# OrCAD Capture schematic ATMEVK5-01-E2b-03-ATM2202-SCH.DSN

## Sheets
1 1. TITLE: title: ATM2202 EVALUATION BOARD; rev: E2b-03
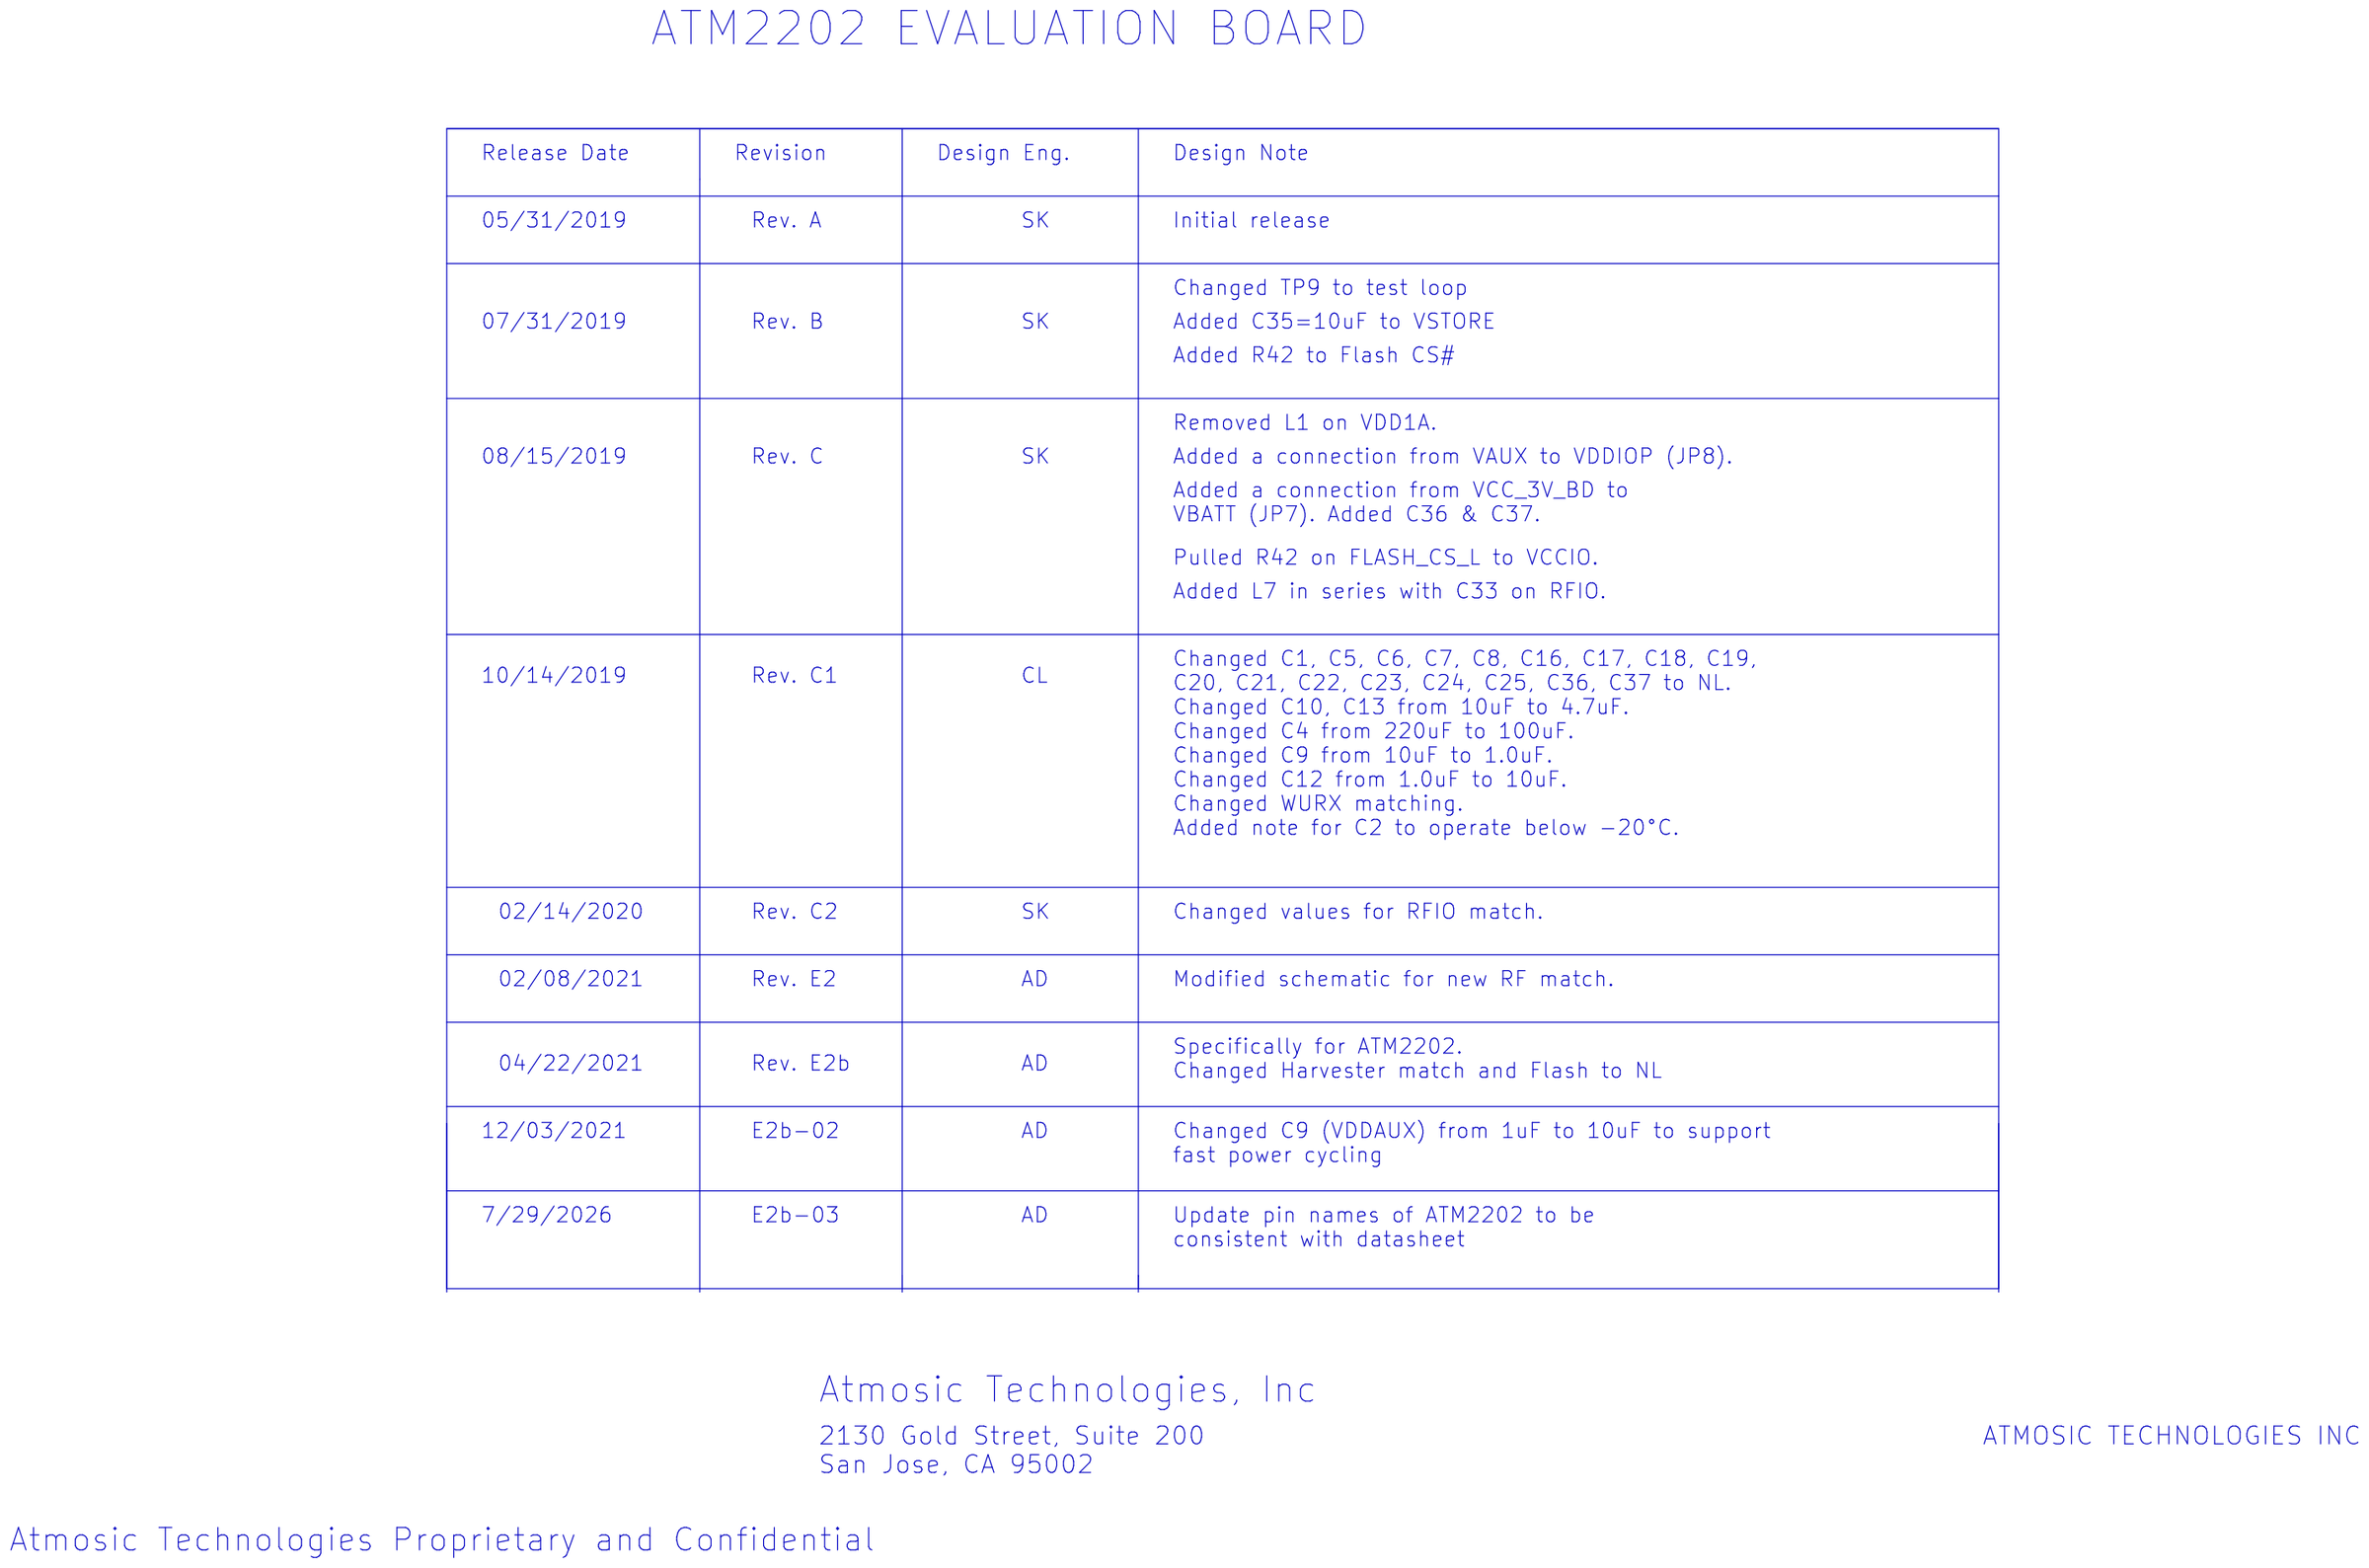
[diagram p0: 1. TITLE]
2 2. ATM2202: size B
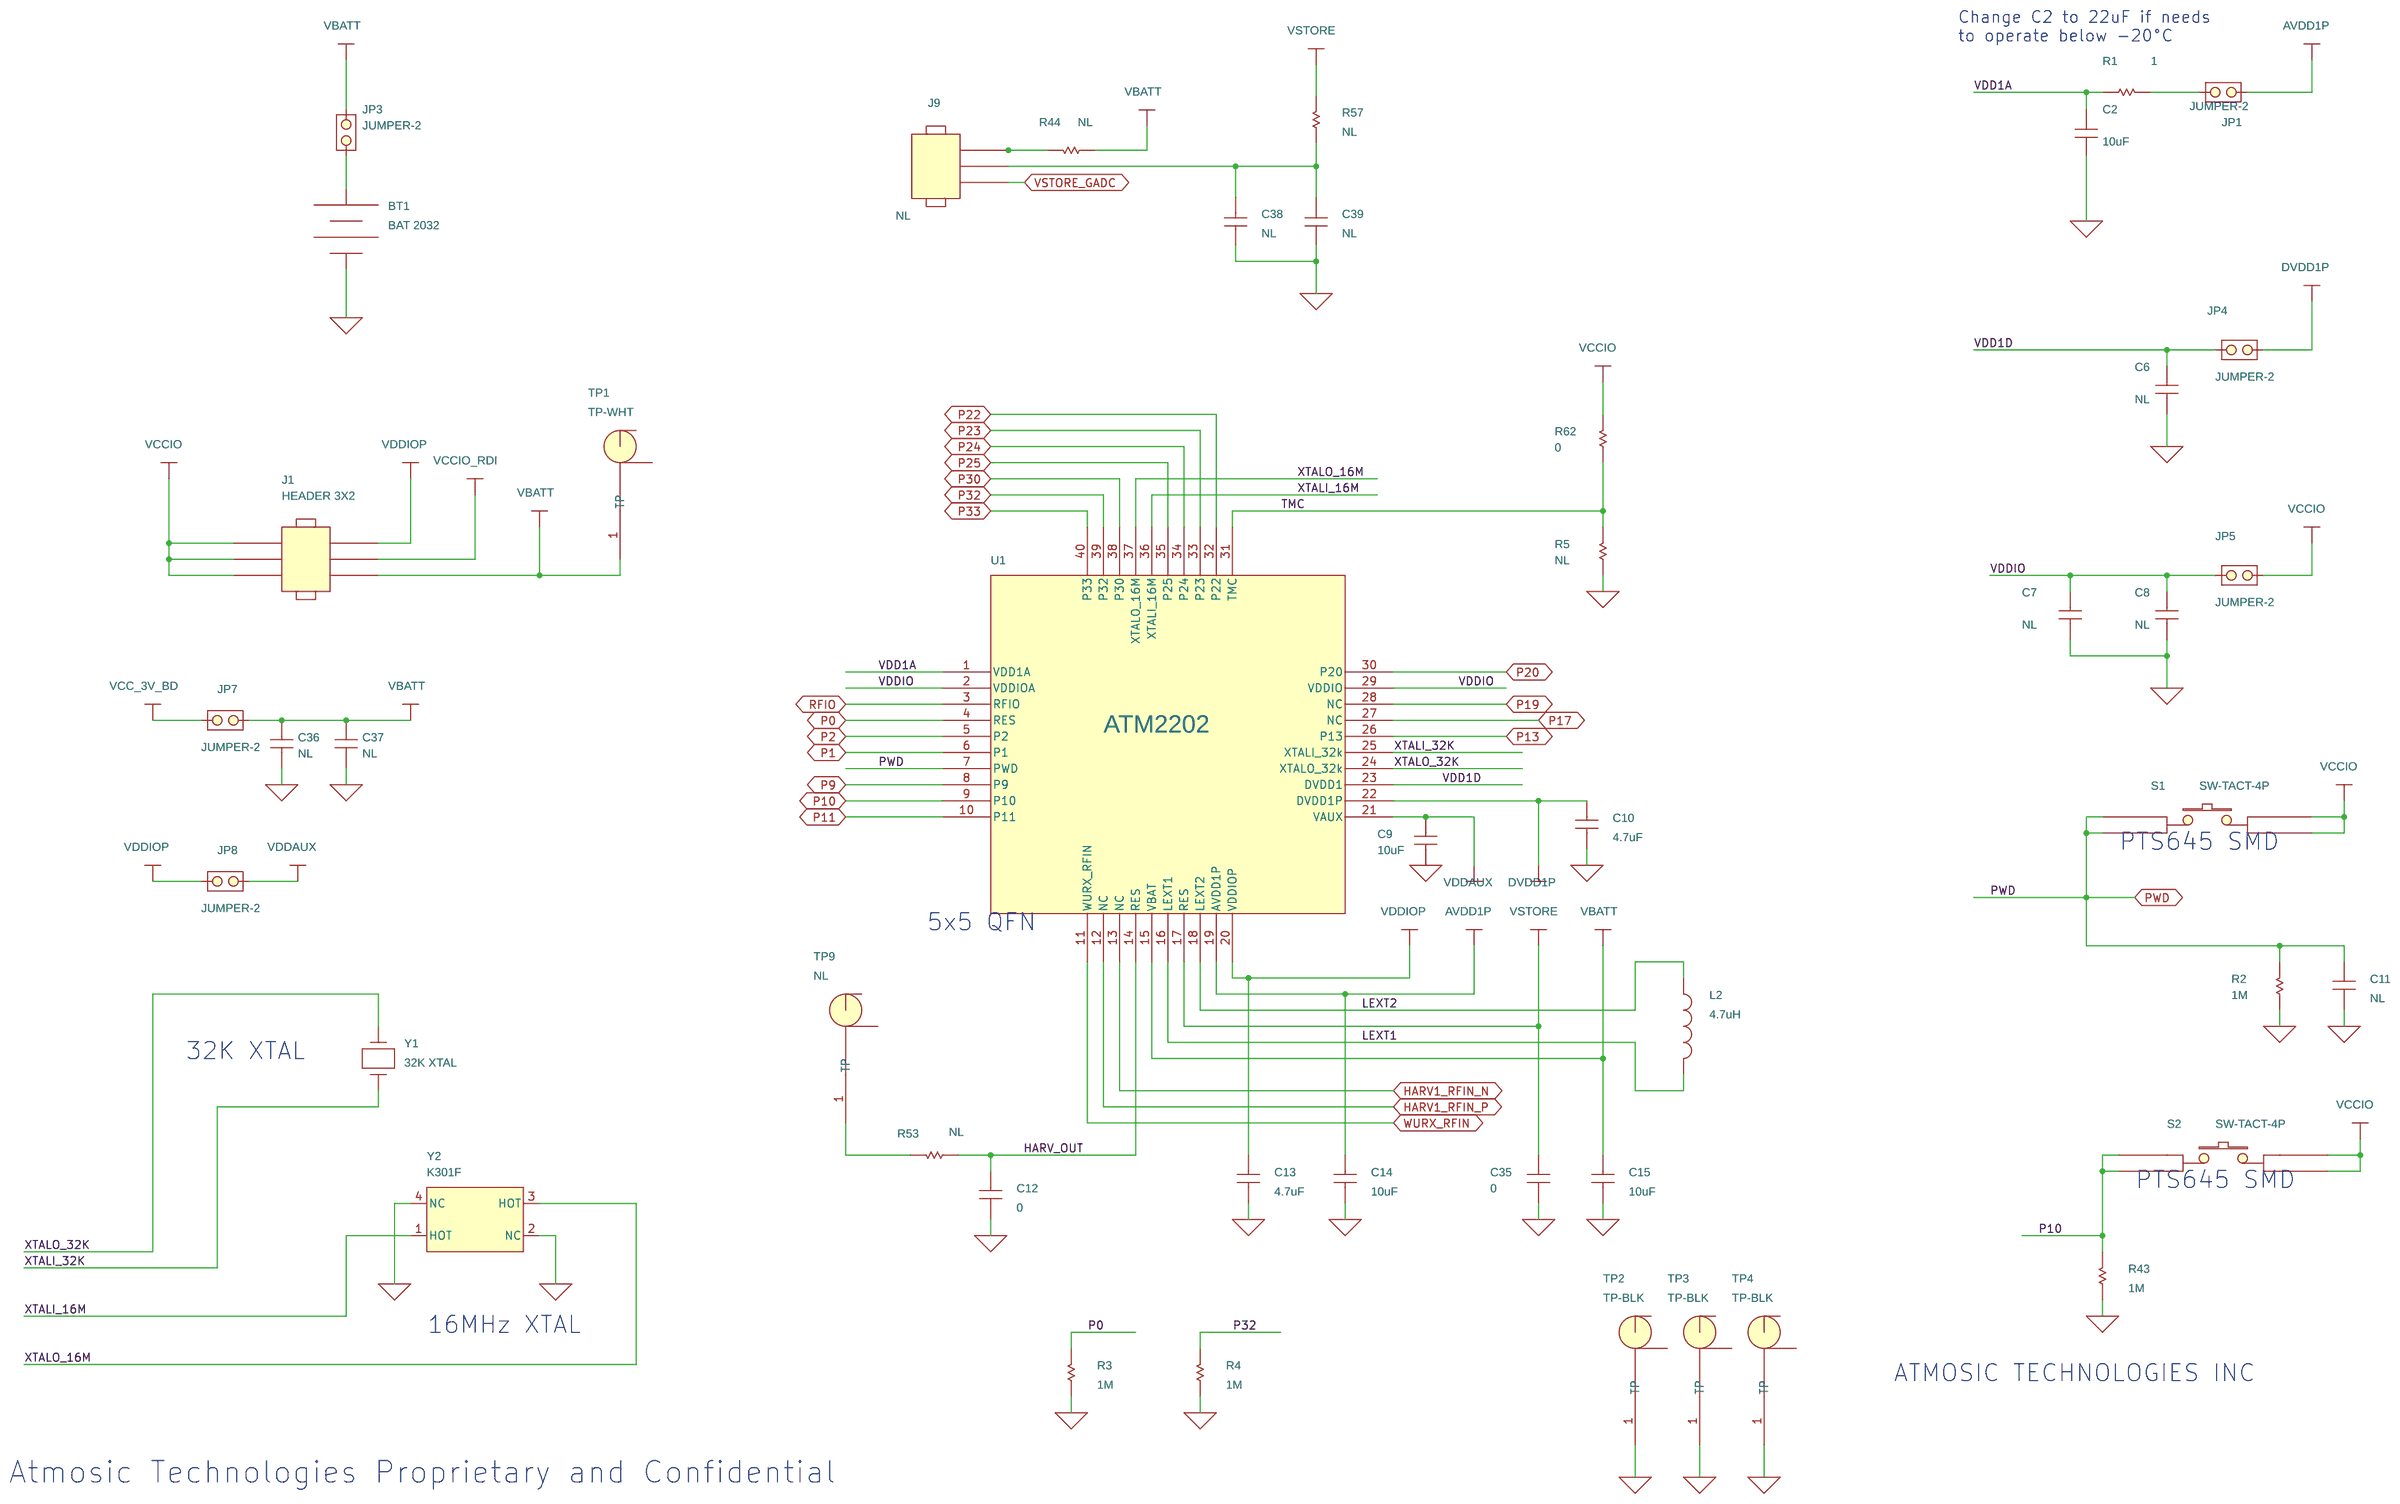
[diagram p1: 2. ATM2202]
3 4. RF (RFIO/WuRX/HARV): size B
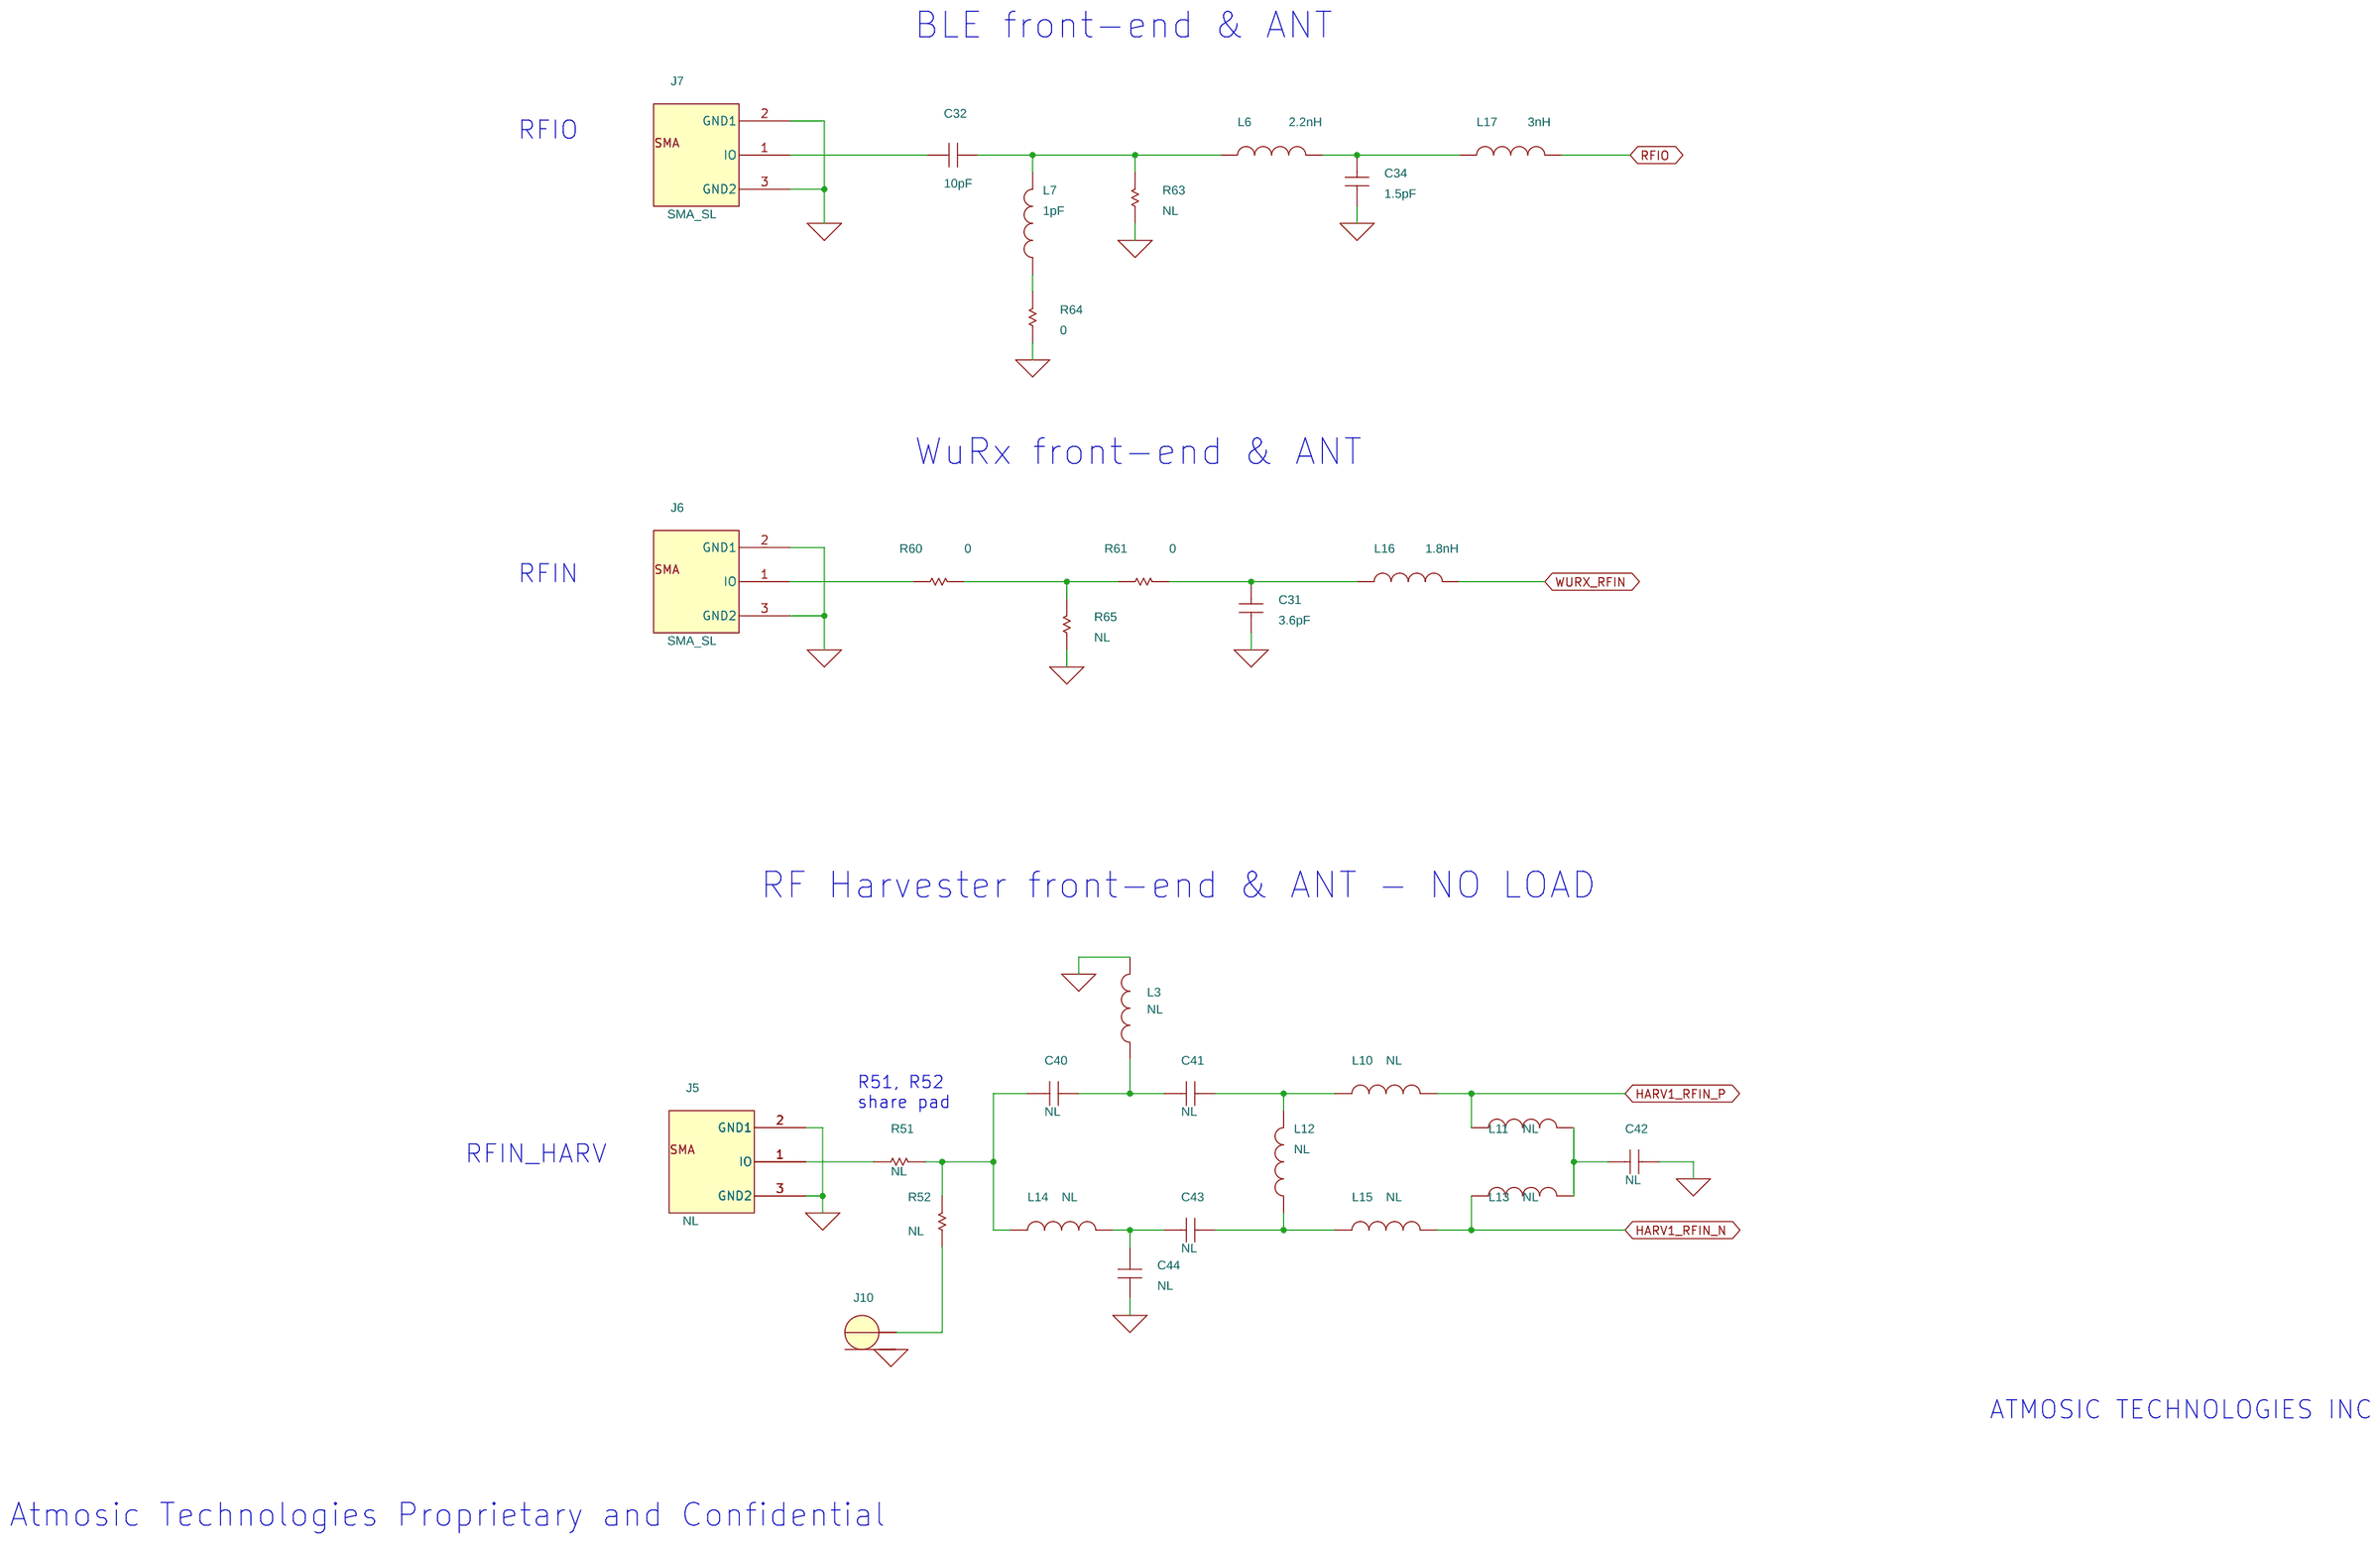
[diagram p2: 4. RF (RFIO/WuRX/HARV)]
4 3. DIGITAL (GPIO/FLASH/CONN): size B
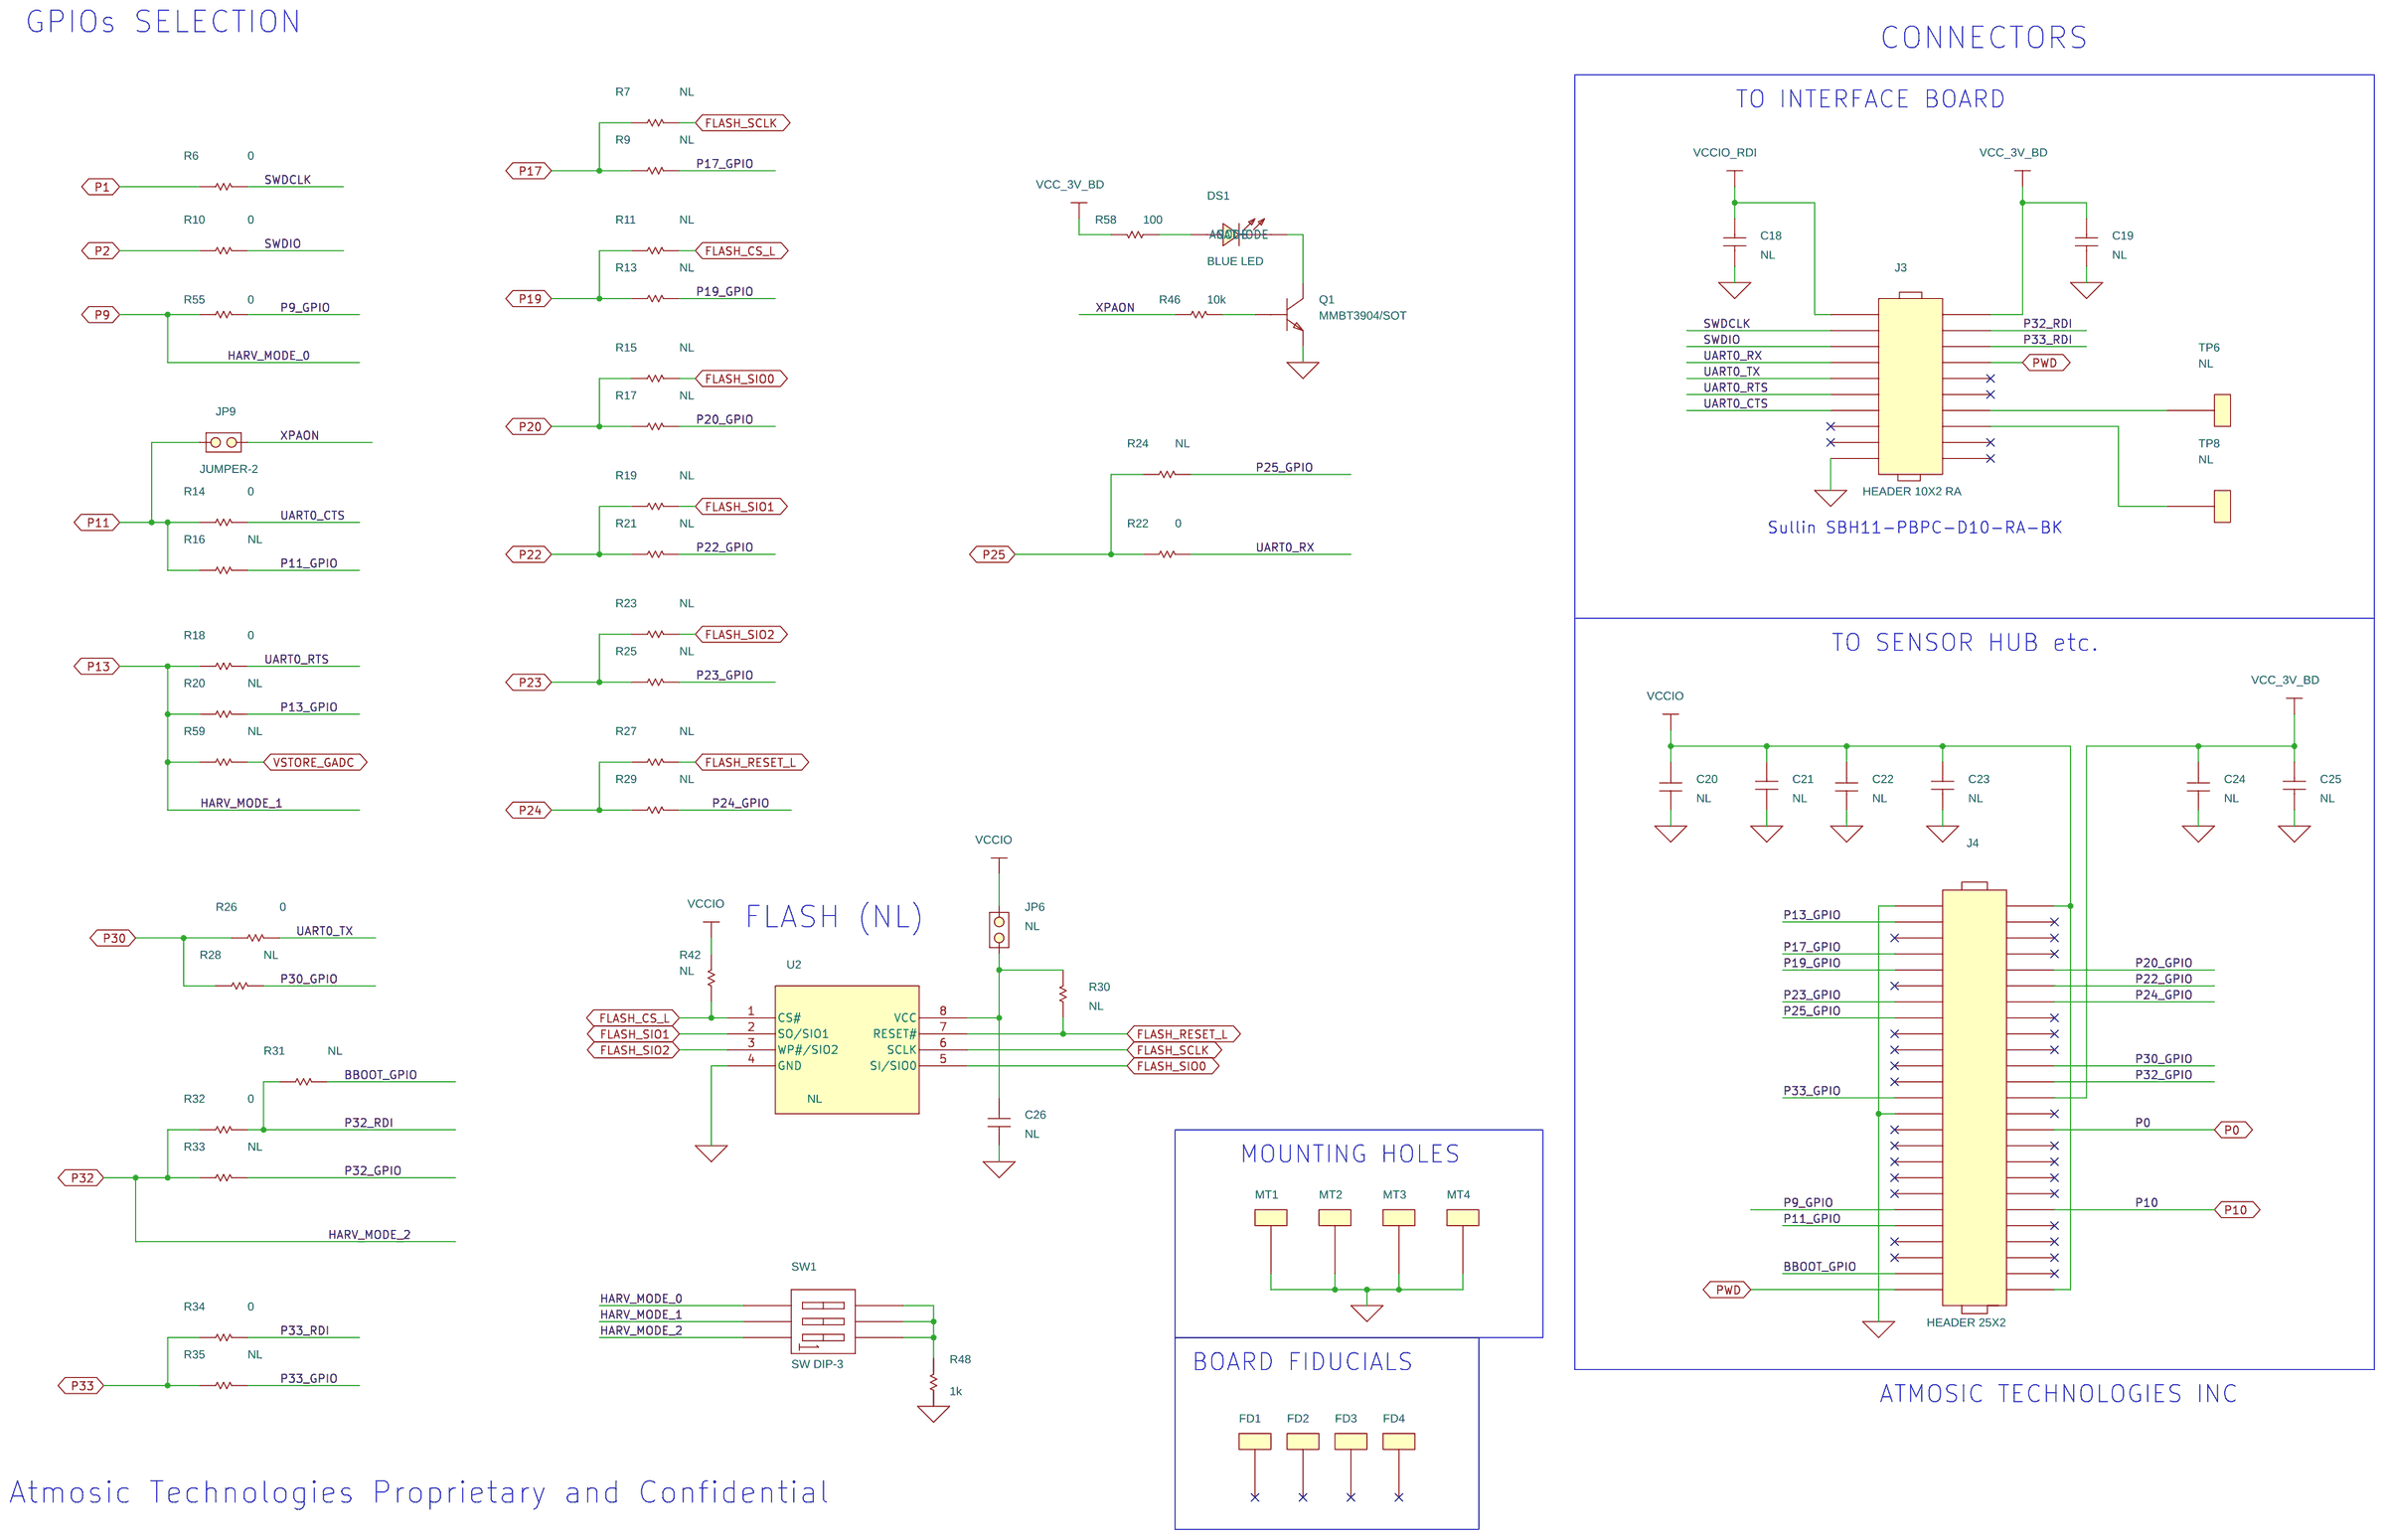
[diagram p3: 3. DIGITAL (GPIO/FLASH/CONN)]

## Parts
sheet 2. ATM2202
BT1  BAT 2032  [BAT-HOLDER-2032]
C2  10uF  [0402]
C6  NL  [0402]
C7  NL  [0402]
C8  NL  [0402]
C9  10uF  [0402]
C10  4.7uF  [0402]
C11  NL  [0402]
C12  0  [0402]
C13  4.7uF  [0402]
C14  10uF  [0402]
C15  10uF  [0402]
C35  0  [0402]
C36  NL  [0402]
C37  NL  [0402]
C38  NL  [1206]
C39  NL  [1206]
J1  HEADER 3X2  [HDR3X2]
J9  NL  [HDR1X3]
JP1  JUMPER-2  [HDR1X2]
JP3  JUMPER-2  [HDR1X2]
JP4  JUMPER-2  [HDR1X2]
JP5  JUMPER-2  [HDR1X2]
JP7  JUMPER-2  [HDR1X2]
JP8  JUMPER-2  [HDR1X2]
L2  4.7uH  [IND-2016-2]
R1  1  [0402]
R2  1M  [0402]
R3  1M  [0402]
R4  1M  [0402]
R5  NL  [0402]
R43  1M  [0402]
R44  NL  [0402]
R53  NL  [0402]
R57  NL  [0603]
R62  0  [0402]
S1  SW-TACT-4P  [SWI-SM-PTS645]
S2  SW-TACT-4P  [SWI-SM-PTS645]
TP1  TP-WHT  [TESTPIN]
TP2  TP-BLK  [TESTPIN]
TP3  TP-BLK  [TESTPIN]
TP4  TP-BLK  [TESTPIN]
TP9  NL  [TESTPIN]
U1  ATM2202  [QFN-40-5X5-0.4MM]
Y1  32K XTAL  [XTAL-SMD2-3.2X1.5MM]
Y2  K301F  [XTAL-ECX-2236]
sheet 3. DIGITAL (GPIO/FLASH/CONN)
C18  NL  [0402]
C19  NL  [0402]
C20  NL  [0402]
C21  NL  [0402]
C22  NL  [0402]
C23  NL  [0402]
C24  NL  [0402]
C25  NL  [0402]
C26  NL  [0402]
DS1  BLUE LED  [LED-0603]
FD1  NL  [FID-G]
FD2  NL  [FID-G]
FD3  NL  [FID-G]
FD4  NL  [FID-G]
J3  HEADER 10X2 RA  [HDR10X2-RT]
J4  HEADER 25X2  [HDR25X2]
JP6  NL  [HDR1X2]
JP9  JUMPER-2  [HDR1X2]
MT1  NL  [HOLE-250R125]
MT2  NL  [HOLE-250R125]
MT3  NL  [HOLE-250R125]
MT4  NL  [HOLE-250R125]
Q1  MMBT3904/SOT  [TRA-SOT23]
R6  0  [0402]
R7  NL  [0402]
R9  NL  [0402]
R10  0  [0402]
R11  NL  [0402]
R13  NL  [0402]
R14  0  [0402]
R15  NL  [0402]
R16  NL  [0402]
R17  NL  [0402]
R18  0  [0402]
R19  NL  [0402]
R20  NL  [0402]
R21  NL  [0402]
R22  0  [0402]
R23  NL  [0402]
R24  NL  [0402]
R25  NL  [0402]
R26  0  [0402]
R27  NL  [0402]
R28  NL  [0402]
R29  NL  [0402]
R30  NL  [0402]
R31  NL  [0402]
R32  0  [0402]
R33  NL  [0402]
R34  0  [0402]
R35  NL  [0402]
R42  NL  [0402]
R46  10k  [0402]
R48  1k  [0402]
R55  0  [0402]
R58  100  [0402]
R59  NL  [0402]
SW1  SW DIP-3  [SW-DIP-219-3]
TP6  NL  [TESTPAD50]
TP8  NL  [TESTPAD50]
U2  NL  [SO8NB]
sheet 4. RF (RFIO/WuRX/HARV)
C31  3.6pF  [0402]
C32  10pF  [0402]
C34  1.5pF  [0402]
C40  NL  [0402]
C41  NL  [0402]
C42  NL  [0402]
C43  NL  [0402]
C44  NL  [0402]
J5  NL  [SMA-RA]
J6  SMA_SL  [SMA-RA]
J7  SMA_SL  [SMA-RA]
J10  NL  [CON-HRS-UFL]
L3  NL  [0402]
L6  2.2nH  [0402]
L7  1pF  [0402]
L10  NL  [0402]
L11  NL  [0402]
L12  NL  [0402]
L13  NL  [0402]
L14  NL  [0402]
L15  NL  [0402]
L16  1.8nH  [0402]
L17  3nH  [0402]
R51  NL  [0402]
R52  NL  [0402]
R60  0  [0402]
R61  0  [0402]
R63  NL  [0402]
R64  0  [0402]
R65  NL  [0402]

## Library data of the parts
BT1 = BAT
C2 C6-C15 C18-C26 C31 C32 C34-C44 = SMALL_CAP
J1 = HEADER_3X2
J9 = HEADER_3
JP1 JP3-JP9 = JUMPER-2
L2 L3 L6 L7 L10-L17 = INDUCTOR
R1-R7 R9-R11 R13-R35 R42-R44 R46 R48 R51-R53 R55 R57-R65 = SMALL_R1
S1 S2 = SW-TACT-4P-5
TP1-TP4 TP9 = TP
U1 = Sydney_2_0.0_QFN_5X5
Y1 = XTAL
Y2 = XTAL-OSC-4P_0
DS1 = LED
FD1-FD4 MT1-MT4 TP6 TP8 = TEST_POINT
J3 = HEADER_10X2
J4 = HEADER_25X2
Q1 = MMBT3904_SOT
SW1 = SW_DIP-3
U2 = LM258DRG3_0
J5-J7 = SMA_SL
J10 = CON_RF_3PIN

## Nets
AVDD1P: C14.1 JP1.1 U1.19(AVDD1P)
DVDD1P: C10.1 JP4.1 U1.22(DVDD1P)
GND_SIGNAL: BT1.2(NEG) C2.1 C6.2 C7.2 C8.2 C9.2 C10.2 C11.2 C12.2 C13.2 C14.2 C15.2 C18.2 C19.2 C20.1 C21.2 C22.1 C23.2 C24.1 C25.2 C26.1 C31.1 C34.1 C35.2 C36.2 C37.2 C38.1 C39.1 C42.1 C44.1 J3.19 J4.1 J4.27 J5.2(GND1) J5.3(GND2) J6.2(GND1) J6.3(GND2) J7.2(GND1) J7.3(GND2) J10.2 J10.3 L3.2 MT1.1 MT2.1 MT3.1 MT4.1 Q1.2(E) R2.1 R3.1 R4.1 R5.1 R43.1 R48.1 R63.2 R64.2 R65.2 TP2.1(TP) TP3.1(TP) TP4.1(TP) U2.4(GND) Y2.2(NC) Y2.4(NC)
VBATT: C15.1 C36.1 C37.1 J1.5 JP3.1 JP7.2 R44.1 TP1.1(TP) U1.15(VBAT)
VCC_3V_BD: C19.1 C24.2 C25.1 J3.2 J4.26 JP7.1 R58.2
VCCIO: C20.2 C21.1 C22.2 C23.1 J1.2 J1.4 J1.6 J4.2 J4.50 JP5.1 JP6.2 R42.1 R62.2 S1.3 S1.4 S2.3 S2.4
VCCIO_RDI: C18.1 J1.3 J3.1
VDD1A: C2.2 R1.1 U1.1(VDD1A)
VDD1D: C6.1 JP4.2 U1.23(DVDD1)
VDDAUX: C9.1 JP8.2 U1.21(VAUX)
VDDIO: C7.1 C8.1 JP5.2 U1.2(VDDIOA) U1.29(VDDIO)
VDDIOP: C13.1 J1.1 JP8.1 U1.20(VDDIOP)
BBOOT_GPIO: J4.47 R31.2
FLASH_CS_L: R11.2 R42.2 U2.1(CS#)
FLASH_RESET_L: R27.2 R30.2 U2.7(RESET#)
FLASH_SCLK: R7.2 U2.6(SCLK)
FLASH_SIO0: R15.2 U2.5(SI/SIO0)
FLASH_SIO1: R19.2 U2.2(SO/SIO1)
FLASH_SIO2: R23.2 U2.3(WP#/SIO2)
HARV1_RFIN_N: L13.1 L15.2 U1.13(NC)
HARV1_RFIN_P: L10.2 L11.1 U1.12(NC)
HARV_OUT: C12.1 R53.1 U1.14(RES)
LEXT1: L2.2 U1.16(LEXT1)
LEXT2: L2.1 U1.18(LEXT2)
P0: J4.30 R3.2 U1.4(RES)
P1: R6.1 U1.6(P1)
P2: R10.1 U1.5(P2)
P9: R55.1 SW1.4(B3) U1.8(P9)
P9_GPIO: J4.39 R55.2
P10: J4.40 R43.2 S2.1 S2.2 U1.9(P10)
P11: JP9.1 R14.1 R16.1 U1.10(P11)
P11_GPIO: J4.41 R16.2
P13: R18.1 R20.1 R59.1 SW1.5(B2) U1.26(P13)
P13_GPIO: J4.3 R20.2
P17: R7.1 R9.1 U1.27(NC)
P17_GPIO: J4.7 R9.2
P19: R11.1 R13.1 U1.28(NC)
P19_GPIO: J4.9 R13.2
P20: R15.1 R17.1 U1.30(P20)
P20_GPIO: J4.10 R17.2
P22: R19.1 R21.1 U1.32(P22)
P22_GPIO: J4.12 R21.2
P23: R23.1 R25.1 U1.33(P23)
P23_GPIO: J4.13 R25.2
P24: R27.1 R29.1 U1.34(P24)
P24_GPIO: J4.14 R29.2
P25: R22.1 R24.1 U1.35(P25)
P25_GPIO: J4.15 R24.2
P30: R26.1 R28.1 U1.38(P30)
P30_GPIO: J4.22 R28.2
P32: R4.2 R32.1 R33.1 SW1.6(B1) U1.39(P32)
P32_GPIO: J4.24 R33.2
P32_RDI: J3.4 R31.1 R32.2
P33: R34.1 R35.1 U1.40(P33)
P33_GPIO: J4.25 R35.2
P33_RDI: J3.6 R34.2
PWD: C11.1 J3.8 J4.49 R2.2 S1.1 S1.2 U1.7(PWD)
RFIO: L17.2 U1.3(RFIO)
SWDCLK: J3.3 R6.2
SWDIO: J3.5 R10.2
TMC: R5.2 R62.1 U1.31(TMC)
UART0_CTS: J3.13 R14.2
UART0_RTS: J3.11 R18.2
UART0_RX: J3.7 R22.2
UART0_TX: J3.9 R26.2
VSTORE: C35.1 R57.2 U1.17(RES)
VSTORE_GADC: J9.1 R59.2
WURX_RFIN: L16.2 U1.11(WURX_RFIN)
XPAON: JP9.2 R46.1
XTALI_16M: U1.36(XTALI_16M) Y2.1(HOT)
XTALI_32K: U1.25(XTALI_32k) Y1.1
XTALO_16M: U1.37(XTALO_16M) Y2.3(HOT)
XTALO_32K: U1.24(XTALO_32k) Y1.2
N16200462: R60.1 R61.2 R65.1
N16200498: C32.1 L6.1 L7.2 R63.1
N16200558: C32.2 J7.1(IO)
N16200576: C34.2 L6.2 L17.1
N16200650: J6.1(IO) R60.2
N16200658: C31.2 L16.1 R61.1
N16780047: C26.2 JP6.1 R30.1 U2.8(VCC)
N16785695: J3.14 TP6.1
N16785697: J3.16 TP8.1
N16793799: JP1.2 R1.2
N16795986: BT1.1(POS) JP3.2
N16841151: C38.2 C39.2 J9.2 R57.1
N16841225: J9.3 R44.2
N16841429: R53.2 TP9.1(TP)
N16842117: DS1.2(ANODE) R58.1
N16842119: DS1.1(CATHODE) Q1.3(C)
N16842134: Q1.1(B) R46.2
N16842294: R48.2 SW1.1(A1) SW1.2(A2) SW1.3(A3)
N16842907: C40.1 C41.2 L3.1
N16842934: C40.2 L14.1 R51.2 R52.2
N16842944: C41.1 L10.1 L12.2
N16842987: C42.2 L11.2 L13.2
N16843001: J5.1(IO) R51.1
N16843065: C43.1 L12.1 L15.1
N16843074: C43.2 C44.2 L14.2
N16843090: J10.1 R52.1
N16848500: L7.1 R64.1

Not connected (* = marked no-connect by the designer): FD1 1*; FD2 1*; FD3 1*; FD4 1*; J3 10* 12* 15* 17* 18* 20*; J4 4* 5* 6* 8* 11* 16* 17* 18* 19* 20* 21* 23* 28* 29* 31* 32* 33* 34* 35* 36* 37* 38* 42* 43* 44* 45* 46* 48*

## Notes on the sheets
sheet 1
- ATM2202 EVALUATION BOARD
- Release Date
- Revision
- Design Eng.
- Design Note
- 05/31/2019
- Rev. A
- SK
- Initial release
- Changed TP9 to test loop
- 07/31/2019
- Rev. B
- SK
- Added C35=10uF to VSTORE
- Added R42 to Flash CS#
- Removed L1 on VDD1A.
- 08/15/2019
- Rev. C
- SK
- Added a connection from VAUX to VDDIOP (JP8).
- Added a connection from VCC_3V_BD to
  VBATT (JP7). Added C36 & C37.
- Pulled R42 on FLASH_CS_L to VCCIO.
- Added L7 in series with C33 on RFIO.
- Changed C1, C5, C6, C7, C8, C16, C17, C18, C19,
  C20, C21, C22, C23, C24, C25, C36, C37 to NL.
  Changed C10, C13 from 10uF to 4.7uF.
  Changed C4 from 220uF to 100uF.
  Changed C9 from 10uF to 1.0uF.
  Changed C12 from 1.0uF to 10uF.
  Changed WURX matching.
  Added note for C2 to operate below -20°C.
- 10/14/2019
- Rev. C1
- CL
- 02/14/2020
- Rev. C2
- SK
- Changed values for RFIO match.
- 02/08/2021
- Rev. E2
- AD
- Modified schematic for new RF match.
- Specifically for ATM2202.
  Changed Harvester match and Flash to NL
- 04/22/2021
- Rev. E2b
- AD
- 12/03/2021
- E2b-02
- AD
- Changed C9 (VDDAUX) from 1uF to 10uF to support
  fast power cycling
- 7/29/2026
- E2b-03
- AD
- Update pin names of ATM2202 to be
  consistent with datasheet
- Atmosic Technologies, Inc
- 2130 Gold Street, Suite 200
  San Jose, CA 95002
- ATMOSIC TECHNOLOGIES INC
- Atmosic Technologies Proprietary and Confidential
sheet 2
- Change C2 to 22uF if needs
  to operate below -20°C
- PTS645 SMD
- 5x5 QFN
- 32K XTAL
- PTS645 SMD
- 16MHz XTAL
- ATMOSIC TECHNOLOGIES INC
- Atmosic Technologies Proprietary and Confidential
sheet 3
- BLE front-end & ANT
- RFIO
- WuRx front-end & ANT
- RFIN
- RF Harvester front-end & ANT - NO LOAD
- R51, R52
  share pad
- RFIN_HARV
- ATMOSIC TECHNOLOGIES INC
- Atmosic Technologies Proprietary and Confidential
sheet 4
- GPIOs SELECTION
- CONNECTORS
- TO INTERFACE BOARD
- Sullin SBH11-PBPC-D10-RA-BK
- TO SENSOR HUB etc.
- FLASH (NL)
- MOUNTING HOLES
- BOARD FIDUCIALS
- ATMOSIC TECHNOLOGIES INC
- Atmosic Technologies Proprietary and Confidential
